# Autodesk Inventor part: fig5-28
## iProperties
Created: 2004-05
Part Number: fig5-28
Document SubType Name: Modeling
Designer: CADCIM Technologies
Manufacturer: Standard
Standards Organization: Custom
Density: 1 g/cm^3
Author: CADCIM Technologies
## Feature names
1. Extrusion1
2. Extrusion2
3. Hole1
4. Fillet5
